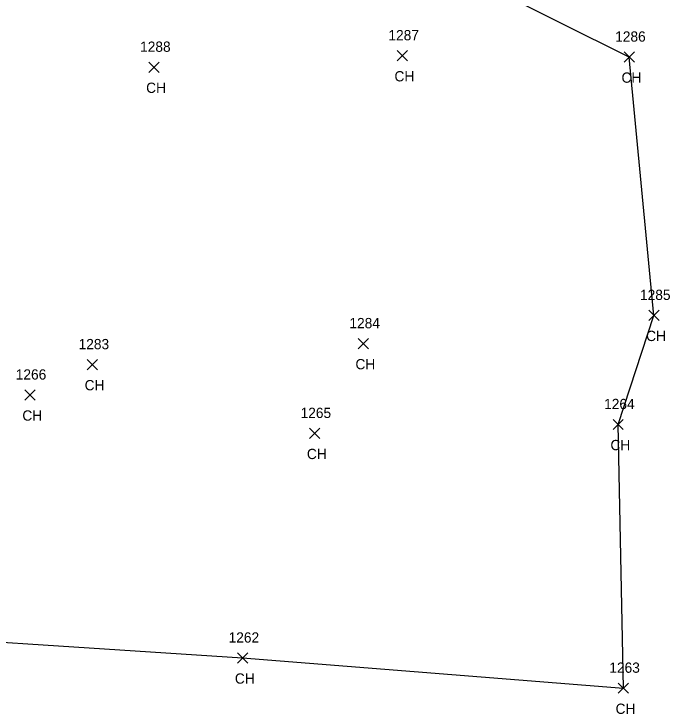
# Model space of a CAD drawing. Extents: x 1715662 to 1717487, y 887396 to 890004.
# Drawn here: x 1717358.8 to 1717486.6, y 888056.1 to 888192.4 of the extents above; entities that cross this region are included whole.
import ezdxf

# ---------------------------------------------------------------- set-up
doc = ezdxf.new("R2010")
doc.units = 0
for name, color, linetype in [('L_A', 7, 'Continuous'), ('L_I', 7, 'Continuous'), ('L_TIC', 7, 'Continuous'), ('LSOGP', 7, 'Continuous')]:
    doc.layers.add(name, color=color, linetype=linetype)

msp = doc.modelspace()

# ---------------------------------------------------------------- linework, layer by layer
at = {"layer": 'L_TIC'}
for points in [[(1717433.43, 888183.28), (1717435.43, 888185.28)], [(1717435.43, 888183.28), (1717433.43, 888185.28)], [(1717477.65, 888183.02), (1717479.65, 888185.02)], [(1717479.65, 888183.02), (1717477.65, 888185.02)], [(1717385.06, 888181.04), (1717387.06, 888183.04)], [(1717387.06, 888181.04), (1717385.06, 888183.04)], [(1717482.45, 888132.72), (1717484.45, 888134.72)], [(1717484.45, 888132.72), (1717482.45, 888134.72)], [(1717425.83, 888127.22), (1717427.83, 888129.22)], [(1717427.83, 888127.22), (1717425.83, 888129.22)], [(1717373.08, 888123.13), (1717375.08, 888125.13)], [(1717375.08, 888123.13), (1717373.08, 888125.13)], [(1717360.95, 888117.22), (1717362.95, 888119.22)], [(1717362.95, 888117.22), (1717360.95, 888119.22)], [(1717475.5, 888111.47), (1717477.5, 888113.47)], [(1717477.5, 888111.47), (1717475.5, 888113.47)], [(1717416.37, 888109.74), (1717418.37, 888111.74)], [(1717418.37, 888109.74), (1717416.37, 888111.74)], [(1717402.35, 888066.01), (1717404.35, 888068.01)], [(1717404.35, 888066.01), (1717402.35, 888068.01)], [(1717476.51, 888060.13), (1717478.51, 888062.13)], [(1717478.51, 888060.13), (1717476.51, 888062.13)]]:
    msp.add_lwpolyline(points, dxfattribs=at)
at = {"layer": 'LSOGP'}
msp.add_lwpolyline([(1717315.64, 888072.73), (1717403.35, 888067.01), (1717477.51, 888061.13), (1717476.5, 888112.47), (1717483.45, 888133.72), (1717478.65, 888184.02), (1717438.03, 888204.25)], dxfattribs=at)

# ---------------------------------------------------------------- texts
at = {"layer": 'L_A'}
for p in [(1717432.92, 888179.28), (1717477.14, 888179.02), (1717384.55, 888177.04), (1717481.94, 888128.72), (1717425.32, 888123.22), (1717372.57, 888119.13), (1717360.44, 888113.22), (1717474.99, 888107.47), (1717415.86, 888105.74), (1717401.83, 888062.01), (1717475.99, 888056.13)]:
    msp.add_text('CH', height=2, dxfattribs=at).set_placement(p)
at = {"layer": 'L_I'}
for s, p in [('1287', (1717431.74, 888187.28)), ('1286', (1717475.91, 888187.02)), ('1288', (1717383.37, 888185.04)), ('1285', (1717480.75, 888136.72)), ('1284', (1717424.14, 888131.22)), ('1283', (1717371.39, 888127.13)), ('1266', (1717359.15, 888121.22)), ('1264', (1717473.76, 888115.47)), ('1265', (1717414.63, 888113.74)), ('1262', (1717400.61, 888070.01)), ('1263', (1717474.77, 888064.13))]:
    msp.add_text(s, height=2, dxfattribs=at).set_placement(p)

doc.saveas('drawing.dxf')
